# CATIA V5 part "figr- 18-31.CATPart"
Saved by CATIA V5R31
Part number: Part1
Bounding box of the stored display mesh (mm): x -37.5 to 37.5, y -50 to 50, z 0 to 59.069
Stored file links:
  D:\PROJECTS\Project 2021\US EDITION\CATIA V5 6R 2021\Resources\Part Files\c18_catia_v6_6r2021_prt\figr- 18-31.CATPart
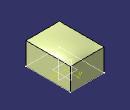
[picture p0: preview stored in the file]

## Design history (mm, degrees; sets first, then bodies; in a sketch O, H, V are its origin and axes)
Set1
  Sketch1 on xy-plane, origin (0, 0, 0), H (1, 0, 0), V (0, 1, 0)
    line L1 (37.5, 50) -> (37.5, -50)
    line L2 (37.5, -50) -> (-37.5, -50)
    line L3 (-37.5, -50) -> (-37.5, 50)
    line L4 (-37.5, 50) -> (37.5, 50)
    length L4 = 75
    length L1 = 100
    vertical: L1 V, L3 V
    horizontal: L2 H, L4 H
    equidistance: L1 L3 O, L2 L4 O
  Extrude1: Element1 Sketch1, Lim1 50, Lim2 0
  DatumSurface1
Body1 (main body)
